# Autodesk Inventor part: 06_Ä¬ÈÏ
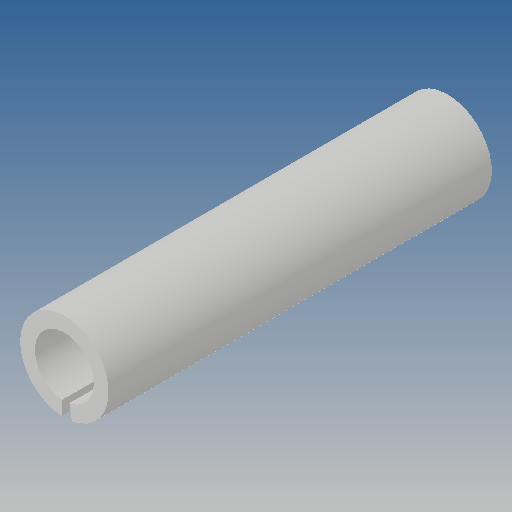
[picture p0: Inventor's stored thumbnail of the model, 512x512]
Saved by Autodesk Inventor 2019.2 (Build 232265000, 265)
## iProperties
Created: 2010-06
Part Number: 06_Ä¬ÈÏ
Material: Ogólny
Document SubType Name: Modeling
Designer: CADENGINEERING4
Density: 1 g/cm^3
Appearance: Domyślna
Author: CADENGINEERING4
Revision Number: ÈÎºÎ
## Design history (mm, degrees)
feature "NONE"
node "Bryła1"
